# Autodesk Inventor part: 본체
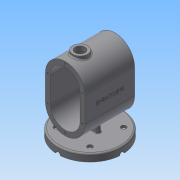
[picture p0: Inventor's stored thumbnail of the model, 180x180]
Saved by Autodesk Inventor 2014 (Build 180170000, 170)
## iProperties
Created: 2016-12
Part Number: 본체
Material: 알루미늄 6061
Document SubType Name: Modeling
Designer: mduedu
Density: 2.71 g/cm^3
Appearance: 기본값
Mass: 1100.74 g
Surface Area: 1091.11 cm^2
Volume: 406.176 cm^3
Author: mduedu
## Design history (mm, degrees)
sketch "스케치1"
  geometry: L1 (40, -25)-(40, 25); L2 (-40, 25)-(-40, -25); L3 (-40, -25)-(40, 25); L4 (40, -25)-(-40, 25); L5 (0, 25)-(0, -25); A1 r 40 centre (0, 25) between (40, 25) and (-40, 25); A2 r 40 centre (0, -25) between (-40, -25) and (40, -25); 1 further point
  constraints: 10 end point, 4 point on circle, 3 tangent, 2 centre point, 2 midpoint, 2 parallel, 1 vertical
  dimensions: "d0" = 130 dimension on A2 A1; "d2" = 80 distance between parallel lines of L1 L2
extrude "돌출1" new body sketch "스케치1" stored distance "d3" = 100; taper "d4" = 0 deg
feature "쉘1" dims "d5" = 10
sketch "스케치2"
  geometry: L1 (-75, 65)-(-90, 65); L2 (-90, 65)-(-90, 0); L3 (-75, 0)-(-75, 65); L4 (-75, 0)-(-90, 0); 1 further point
  constraints: 8 end point, 1 horizontal, 1 horizontal alignment, 1 parallel, 1 perpendicular
  dimensions: "d6" = 90 distance from line of L2 point (0, 0); "d83" = 15 distance of L1.start L1.end; "d84" = 130 diameter of L1 L4
revolve "회전1" sketch "스케치2" stored, may be unused: angle "d85" = 90 deg
fillet "모깎기5" dims "d86" = 3
hole "구멍6" diameter "d89" = 120; stored, may be unused: countersink angle "d93" = 90 deg, drill point angle "d95" = 0 deg; dims "d87" = 10, "d88" = 10, "d90" = 6, "d91" = 4, "d92" = 2, "d94" = 10
sketch "스케치15"
  geometry: L1 (-90, -60)-(-90, 60) reference; C1 r 5 at (-90, 0); 1 further point
  constraints: 1 centre point, 1 horizontal alignment, 1 midpoint
  dimensions: "d96" = 10 diameter of C1
extrude "돌출6" cut sketch "스케치15" stored distance "d97" = 10; taper "d98" = 0 deg
sketch "스케치5"
  geometry: L1 (4, -30)-(-4, -30); L2 (-4, -30)-(-4, 30); L3 (-4, 30)-(4, 30); L4 (4, 30)-(4, -30); L5 (4, -30)-(-4, 30); L6 (-4, -30)-(4, 30); 3 further points
  constraints: 12 end point, 3 midpoint, 2 parallel, 1 coincident, 1 horizontal, 1 perpendicular
  dimensions: "d22" = 8 distance of L2.end L3.end; "d24" = 60 distance of L1.end L2.end
extrude "돌출3" join sketch "스케치5" stored distance "d25" = 80; taper "d26" = 0 deg
feature "면 기울기1" dims angle "d27" = 5 deg
sketch "스케치6"
  geometry: L1 (-18.718, -60.35)-(-20, -75); L2 (-62, -75)-(62, -75) reference; A1 r 40 centre (0, -25) between (-40, -25) and (40, -25) reference; 1 further point
  constraints: 2 end point, 1 point on circle, 1 point on line
  dimensions: "d28" = 20 horizontal distance of A1.centre L1.end; "d102" = 85 deg angle of L2 L1
feature "리브1" sketch "스케치6" dims "d30" = 1, "d31" = 8, "d32" = 0, "d33" = 0, "d34" = 1, "d35" = 1
fillet "모깎기2" dims "d36" = 3
fillet "모깎기3" dims "d37" = 1, "d38" = 1
node "작업 평면1"
sketch "스케치9"
  geometry: 1 further point
sketch "스케치7"
  geometry: L1 (40, 50)-(-40, 50) reference; C1 r 15 at (0, 20); 1 further point
  constraints: 1 centre point, 1 vertical alignment
  dimensions: "d40" = 30 diameter of C1; "d41" = 30 distance from line of C1.centre L1
extrude "돌출4" join sketch "스케치7" stored distance "d42" = 80; taper "d43" = 0 deg
hole "구멍2" diameter "d46" = 20; stored, may be unused: countersink angle "d50" = 90 deg, drill point angle "d52" = 118 deg; dims "d44" = 10, "d45" = 10, "d47" = 6, "d48" = 4, "d49" = 2, "d51" = 8
fillet "모깎기4" dims "d53" = 3
node "작업 평면2"
sketch "스케치8"
  geometry: C1 r 15 at (0, 0) reference; C2 r 15 at (0, 0); 1 further point
  constraints: 1 centre point, 1 coincident
  dimensions: "d55" = 30 diameter of C2
extrude "돌출5" cut sketch "스케치8" stored distance "d56" = 80; taper "d57" = 0 deg
chamfer "모따기1" distance "d58" = 1; stored, may be unused: second distance "d59" = 2, angle "d60" = 45 deg
sketch "스케치10"
  geometry: 2 further points
  constraints: 1 coincident, 1 other
feature "엠보싱1" sketch "스케치10" dims "d0" = 130, "d2" = 80, "d61" = 0.5, "d62" = 0
sketch "스케치11"
  geometry: 1 further point
hole "구멍3" sketch "스케치11" at (0, 60) diameter "d63" = 3.242; stored, may be unused: countersink angle "d67" = 90 deg, drill point angle "d69" = 120 deg; dims "d64" = 8.6, "d65" = 4, "d66" = 2, "d68" = 10.6
sketch "스케치12"
  geometry: 1 further point
hole "구멍5" sketch "스케치12" at (0, 60) diameter "d70" = 3.242; stored, may be unused: countersink angle "d74" = 90 deg, drill point angle "d76" = 120 deg; dims "d71" = 8.6, "d72" = 4, "d73" = 2, "d75" = 10.6
sketch "스케치16"
  geometry: L1 (0, 0)-(0, 48); L2 (0, 0)-(-33.941, 33.941); A1 r 48 centre (0, 0) between (0, 48) and (-33.941, 33.941); 2 further points
  constraints: 4 end point, 2 coincident, 2 point on circle, 1 centre point, 1 vertical
  dimensions: "d103" = 96 diameter of A1; "d104" = 45 deg angle of L1 L2
hole "구멍7" sketch "스케치16" at (-33.941, 33.941) diameter "d108" = 10; stored, may be unused: countersink angle "d112" = 90 deg, drill point angle "d114" = 118 deg; dims "d109" = 6, "d110" = 4, "d111" = 2, "d113" = 10
node "솔리드1"
pattern_circular "원형 패턴1" dims angle "d100" = 90 deg
mirror "대칭1"
pattern_linear "직사각형 패턴1"
pattern_linear "직사각형 패턴2"
pattern_circular "원형 패턴2" dims "d35" = 1, angle "d116" = 360 deg
sketch "스케치13"
  geometry: L1 (-40, 25)-(-40, -25) reference; L2 (40, -25)-(40, 25) reference; L3 (35, 25)-(35, -25); L4 (-35, -25)-(-35, 25); A1 r 40 centre (0, 25) between (40, 25) and (-40, 25) reference; A2 r 40 centre (0, -25) between (-40, -25) and (40, -25) reference; A3 r 35 centre (0, 25) between (35, 25) and (-35, 25); A4 r 35 centre (0, -25) between (-35, -25) and (35, -25); 2 further points
  constraints: 5 point on circle, 4 end point, 2 centre point, 3 other
  dimensions: "d77" = 5 distance between parallel lines of L3 L2
sketch "스케치14"
  geometry: L1 (-40, 25)-(-40, -25) reference; L2 (40, -25)-(40, 25) reference; L3 (35, 25)-(35, -25); L4 (-35, -25)-(-35, 25); A1 r 40 centre (0, 25) between (40, 25) and (-40, 25) reference; A2 r 40 centre (0, -25) between (-40, -25) and (40, -25) reference; A3 r 35 centre (0, 25) between (35, 25) and (-35, 25); A4 r 35 centre (0, -25) between (-35, -25) and (35, -25); 2 further points
  constraints: 5 point on circle, 4 end point, 2 centre point, 3 other
  dimensions: "d80" = 5 distance between parallel lines of L2 L3
